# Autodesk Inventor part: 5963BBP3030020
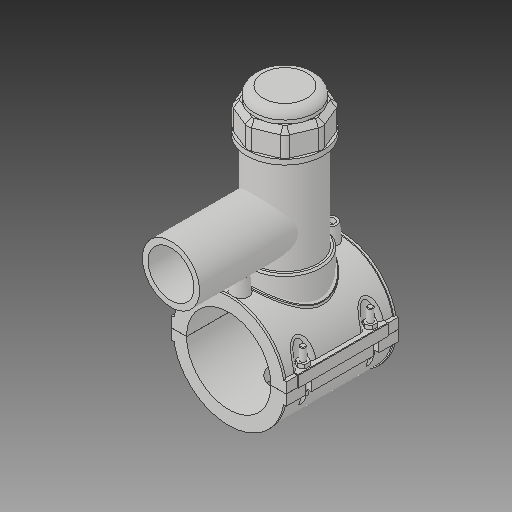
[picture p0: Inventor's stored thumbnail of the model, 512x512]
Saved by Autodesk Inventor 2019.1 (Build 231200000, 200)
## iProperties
Created: 2017-07
Part Number: 5963BBP3030020
Material: Generic
Description: PLASSON TAPPING SADDLE 3''IPS x 2''IPS
Document SubType Name: Modeling
Designer: KIM
Density: 1 g/cm^3
Appearance: Default
Author: KIM
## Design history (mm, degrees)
derived "5963BBP_5963BUP.ipt"
feature "Solid1::5963BBP_5963BUP.ipt"
feature "Solid2::5963BBP_5963BUP.ipt"
feature "Solid3::5963BBP_5963BUP.ipt"
tag "TaggingFeature1"
body "Solid1"
body "Solid2"
body "Solid3"
other parameters: "d_" = 88.7, "B_" = 120.904, "L_" = 118.11, "d_t" = 6, "H_2" = 177.038, "H_1" = 65.024, "d_1" = 60.1, "H_" = 119.888, "d1" = 115.31, "d148" = 1.3305, "d160" = 1.3305, "d169" = 3.2805, "d192" = 6.9984, "d0" = 88.7, "d2" = 120.904, "d3" = 22.175, "d4" = 118.11, "d5" = 0, "d6" = 0.1, "d8" = 0, "d19" = 6, "d20" = 6, "d21" = 70.866, "d23" = 0, "d24" = 35.433, "d26" = 0, "d27" = 3, "d28" = 3, "d29" = 3, "d30" = 29.56667, "d31" = 6, "d32" = 0, "d33" = 0, "d34" = 0.6, "d40" = 59.9612, "d41" = 79.83, "d43" = 0, "d45" = 0, "d47" = 128.521, "d70" = 15, "d72" = 0, "d73" = 6, "d75" = 5, "d76" = 0, "d77" = 4.435, "d78" = 74.35, "d79" = 15, "d80" = 47.244, "d82" = 5 deg, "d84" = 4, "d85" = 14, "d86" = 0, "d87" = 3, "d88" = 0, "d89" = 1, "d90" = 1, "d91" = 94.488, "d92" = 0, "d93" = 0.5, "d94" = 46.68421, "d96" = 117.6162, "d97" = 2.3622, "d98" = 0, "d102" = 0.887, "d120" = 140 deg, "d121" = 24.228, "d122" = 20 deg, "d123" = 230.62, "d124" = 69.186, "d126" = 0, "d143" = 91.361, "d145" = 20.46923, "d149" = 1.3305, "d150" = 22.51615, "d153" = 118.11, "d154" = 0, "d156" = 57.655, "d157" = 160 deg, "d159" = 5.322, "d161" = 1.3305, "d162" = 70.866, "d163" = 0, "d164" = 44.35, "d167" = 8.87, "d168" = 56.24878, "d170" = 3.2805, "d172" = 0, "d173" = 1, "d175" = 44.35, "d176" = 20 deg, "d177" = 6.209, "d178" = 26.61, "d180" = 0, "d183" = 10.644, "d184" = 4.9672, "d185" = 38.38575, "d186" = 38.38575, "d187" = 57.655, "d188" = 7.983, "d189" = 6.209, "d190" = 0, "d191" = 86.4825, "d193" = 6.9984, "d194" = 4.13385, "d195" = 90 deg, "d197" = 0, "d199" = 0, "d200" = 13.305, "d202" = 0, "d203" = 177.038, "d204" = 75.8385, "d205" = 55.881, "d206" = 67.8555, "d207" = 132.7785, "d208" = 138.08964, "d209" = 164.64534, "d210" = 68.6538, "d211" = 79.83, "d212" = 63.864, "d213" = 31.4766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
